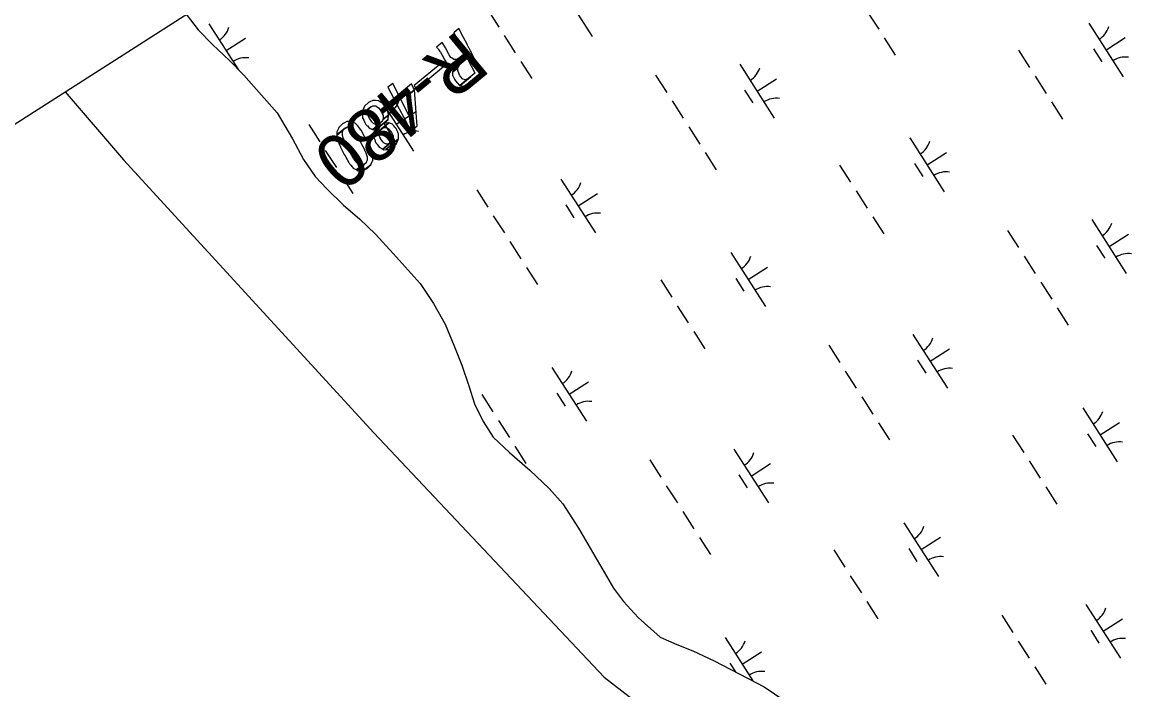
# Model space of a CAD drawing. Extents: x 3962991 to 3983549, y 181631 to 204078.
# Drawn here: x 3969173 to 3970044, y 198215 to 198737 of the extents above; entities that cross this region are included whole.
import ezdxf

# ---------------------------------------------------------------- set-up
doc = ezdxf.new("R2010")
doc.units = 0
for name, color, linetype in [('V-ANNO-MASK', 7, 'Continuous'), ('V-ANNO-MASK2', 7, 'Continuous'), ('V-GRID-FRAM', 7, 'Continuous'), ('V-RIVR-EDGE', 7, 'Continuous'), ('V-RIVR-RANG-IDEN', 7, 'Continuous'), ('V-WETL-SWMP', 7, 'Continuous')]:
    doc.layers.add(name, color=color, linetype=linetype)

msp = doc.modelspace()

# ---------------------------------------------------------------- linework, layer by layer
at = {"layer": 'V-ANNO-MASK2'}
for points in [[(3969516.05, 198730.03), (3969515.13, 198731.81), (3969511.16, 198728.53), (3969512.09, 198726.76), (3969512.29, 198726.38), (3969513.23, 198724.57), (3969513.52, 198724.02), (3969516.02, 198719.23), (3969516.33, 198718.63), (3969517.5, 198716.4), (3969517.98, 198715.47), (3969518.75, 198714), (3969519.3, 198712.94), (3969519.47, 198712.61), (3969519.62, 198712.33), (3969508.77, 198703.36), (3969510.4, 198703.21), (3969513.2, 198704.25), (3969511.77, 198702.61), (3969510.22, 198699.72), (3969510.22, 198699.34), (3969521.52, 198708.68), (3969521.61, 198708.51), (3969522.11, 198707.56), (3969522.93, 198706), (3969523.19, 198705.5), (3969524.82, 198702.38), (3969525.24, 198701.56), (3969526.46, 198699.23), (3969527.35, 198697.54), (3969527.53, 198697.18), (3969527.53, 198697.19), (3969527.61, 198697.04), (3969527.64, 198696.96), (3969515.98, 198687.33), (3969519.53, 198686.56), (3969523.1, 198687.89), (3969526.63, 198690.58), (3969533.62, 198696.36), (3969533.54, 198696.52), (3969532.96, 198697.65), (3969531.6, 198700.24), (3969531.57, 198700.31), (3969531.49, 198700.45), (3969531.3, 198700.81), (3969530.42, 198702.51), (3969529.2, 198704.83), (3969528.78, 198705.65), (3969527.15, 198708.77), (3969526.89, 198709.27), (3969526.07, 198710.84), (3969525.58, 198711.78), (3969525.49, 198711.95), (3969525.35, 198712.22), (3969524.76, 198713.34), (3969524.6, 198713.66), (3969524.13, 198714.55), (3969523.59, 198715.6), (3969523.44, 198715.89), (3969523.26, 198716.22), (3969522.71, 198717.28), (3969521.94, 198718.75), (3969521.46, 198719.67), (3969520.3, 198721.9), (3969519.98, 198722.51), (3969517.48, 198727.3), (3969517.2, 198727.84), (3969516.25, 198729.65)], [(3969503.1, 198719.33), (3969501.97, 198720.94), (3969497.64, 198717.37), (3969498.93, 198715.89), (3969499.17, 198715.55), (3969500.3, 198713.89), (3969500.6, 198713.35), (3969503.18, 198708.63), (3969503.5, 198708.03), (3969504.91, 198706), (3969505.49, 198705.16), (3969506.84, 198704.17), (3969507.8, 198703.45), (3969508.32, 198703.4), (3969508.77, 198703.36), (3969515.88, 198709.23), (3969513.61, 198707.77), (3969513.02, 198707.75), (3969511.09, 198707.68), (3969509.73, 198708.66), (3969508.87, 198709.27), (3969507.52, 198711.35), (3969507.16, 198711.92), (3969504.65, 198716.7), (3969504.35, 198717.23), (3969503.34, 198718.99)], [(3969503.14, 198702.19), (3969501.65, 198705.03), (3969480.2, 198687.32), (3969481.69, 198684.47)], [(3969515.76, 198703.67), (3969518.28, 198706), (3969510.22, 198699.34), (3969510.22, 198699.1), (3969510.21, 198697.74), (3969514.31, 198701.13)], [(3969514.39, 198698.95), (3969514.31, 198701.12), (3969510.21, 198697.74), (3969510.2, 198695.49), (3969510.44, 198694.98), (3969511.98, 198691.77), (3969512.37, 198690.93), (3969514.13, 198689.05), (3969515.42, 198687.68), (3969515.68, 198687.39), (3969515.89, 198687.35), (3969522.42, 198692.75), (3969521.82, 198692.46), (3969520.39, 198691.79), (3969518.13, 198692.35), (3969516.47, 198694.31), (3969515.89, 198695), (3969514.41, 198698.25)], [(3969524.44, 198694.32), (3969522.42, 198692.75), (3969515.89, 198687.35), (3969515.98, 198687.33)], [(3969467.85, 198680.2), (3969463.27, 198688.98), (3969459.6, 198685.94), (3969464.17, 198677.16)], [(3969479.66, 198685.15), (3969477.9, 198688.5), (3969460.48, 198674.11), (3969462.24, 198670.76), (3969476.75, 198682.74), (3969476.92, 198680.97), (3969480.36, 198683.82)], [(3969470.26, 198675.47), (3969469.59, 198676.83), (3969465.93, 198673.81), (3969466.63, 198672.48), (3969473.46, 198659.41), (3969473.63, 198659.06), (3969474.79, 198656.84), (3969474.85, 198656.73), (3969476.27, 198654), (3969479.34, 198656.53), (3969478.1, 198659.41), (3969478.05, 198659.53), (3969476.98, 198661.83), (3969476.81, 198662.18)], [(3969481.61, 198666.14), (3969480.36, 198683.81), (3969476.92, 198680.97), (3969478.46, 198663.54), (3969478.5, 198663.08), (3969478.83, 198660.17), (3969478.85, 198660.03), (3969479.34, 198656.53), (3969476.27, 198654), (3969477.51, 198651.64), (3969482.34, 198655.64), (3969482.12, 198658.83), (3969481.86, 198662.51), (3969481.85, 198662.67), (3969481.64, 198665.67)], [(3969445.31, 198674.55), (3969444.28, 198674.08), (3969441.21, 198671.16), (3969440.56, 198669.72), (3969439.26, 198666.8), (3969439.44, 198665.06), (3969446.09, 198670.55), (3969446.63, 198670.8), (3969446.68, 198670.82), (3969447.84, 198671.36), (3969448.72, 198671.33), (3969450.07, 198671.29), (3969450.68, 198670.88), (3969451.11, 198670.6), (3969452.22, 198669.85), (3969452.28, 198669.8), (3969453.42, 198668.2), (3969454.35, 198666.89), (3969454.38, 198666.84), (3969454.96, 198665.51), (3969455.08, 198665.23), (3969455.71, 198663.8), (3969455.76, 198662.43), (3969455.76, 198662.28), (3969455.8, 198661.13), (3969455.62, 198660.74), (3969460.15, 198664.48), (3969460.09, 198664.67), (3969459.78, 198665.6), (3969459.74, 198665.72), (3969459.38, 198666.83), (3969458.87, 198668.37), (3969458.77, 198668.66), (3969457.98, 198669.81), (3969457.95, 198669.85), (3969457.03, 198671.18), (3969455.91, 198672.8), (3969455.87, 198672.86), (3969454.78, 198673.63), (3969454.36, 198673.92), (3969453.76, 198674.34), (3969453, 198674.87), (3969452.51, 198675.21), (3969452.23, 198675.4), (3969452.21, 198675.41), (3969452, 198675.43), (3969449.88, 198675.57), (3969447.8, 198675.7)], [(3969444.79, 198669.28), (3969446.09, 198670.55), (3969439.45, 198665.06), (3969439.46, 198664.88), (3969439.46, 198664.88), (3969439.46, 198664.86), (3969444.68, 198669.17)], [(3969444.36, 198668.48), (3969444.68, 198669.17), (3969439.46, 198664.86), (3969439.5, 198664.47), (3969439.51, 198664.47), (3969439.57, 198663.78), (3969439.68, 198662.71), (3969439.77, 198661.87), (3969440, 198661.42), (3969440.59, 198660.25), (3969440.63, 198660.18), (3969441.54, 198658.39), (3969441.54, 198658.39), (3969442.29, 198656.92), (3969442.32, 198656.88), (3969443.29, 198655.88), (3969443.49, 198655.66), (3969443.5, 198655.67), (3969444.55, 198654.58), (3969445.3, 198653.8), (3969445.38, 198653.7), (3969446.4, 198653.36), (3969446.6, 198653.29), (3969447.01, 198653.15), (3969447.52, 198652.99), (3969447.67, 198652.93), (3969453.2, 198657.5), (3969452.78, 198657.33), (3969451.39, 198656.77), (3969450.89, 198656.83), (3969450.63, 198656.86), (3969449.38, 198657), (3969449.2, 198657.02), (3969448.32, 198657.7), (3969447.1, 198658.64), (3969446.94, 198658.88), (3969446.16, 198660.06), (3969446.14, 198660.1), (3969445.24, 198661.44), (3969444.45, 198663.34), (3969444.42, 198663.41), (3969443.9, 198664.64), (3969443.87, 198665.26), (3969443.84, 198666.14), (3969443.78, 198667.25)], [(3969425.57, 198658.16), (3969423.99, 198657.31), (3969421.21, 198654.57), (3969420.82, 198653.72), (3969419.52, 198650.95), (3969419.55, 198649.52), (3969419.56, 198648.67), (3969426.27, 198654.21), (3969426.55, 198654.32), (3969428.03, 198654.93), (3969428.63, 198654.85), (3969429.13, 198654.79), (3969430.08, 198654.67), (3969430.96, 198653.97), (3969430.97, 198653.96), (3969432.37, 198652.84), (3969433.11, 198651.74), (3969433.89, 198650.6), (3969434.71, 198649.4), (3969434.79, 198649.27), (3969437.51, 198644.28), (3969437.84, 198643.69), (3969438.45, 198642.55), (3969438.72, 198641.99), (3969438.73, 198641.99), (3969441.08, 198637.19), (3969441.08, 198637.2), (3969441.27, 198636.81), (3969441.82, 198635.69), (3969442.21, 198634.59), (3969442.76, 198633.01), (3969443.25, 198631.62), (3969443.26, 198631.49), (3969443.3, 198630.09), (3969443.31, 198629.48), (3969443.33, 198628.86), (3969442.88, 198627.9), (3969442.88, 198627.91), (3969442.43, 198626.94), (3969440.94, 198625.59), (3969435.35, 198620.97), (3969436.07, 198620.57), (3969437.53, 198620.6), (3969439.77, 198620.65), (3969441.42, 198621.53), (3969446.06, 198625.36), (3969446.4, 198626.13), (3969447.64, 198628.95), (3969447.62, 198630.11), (3969447.61, 198631.09), (3969447.6, 198631.22), (3969447.6, 198631.8), (3969447.58, 198632.38), (3969447.57, 198633), (3969447.42, 198633.49), (3969447.05, 198634.62), (3969447.02, 198634.73), (3969446.56, 198636.15), (3969446.03, 198637.75), (3969445.55, 198638.77), (3969445, 198639.9), (3969444.81, 198640.28), (3969442.49, 198645.1), (3969442.19, 198645.64), (3969441.57, 198646.77), (3969441.24, 198647.36), (3969438.48, 198652.32), (3969438.4, 198652.46), (3969437.53, 198653.61), (3969436.69, 198654.7), (3969435.89, 198655.74), (3969434.81, 198657.14), (3969434.81, 198657.15), (3969433.78, 198657.73), (3969433.12, 198658.09), (3969432.78, 198658.28), (3969432.37, 198658.52), (3969431.93, 198658.77), (3969431.84, 198658.81), (3969431.22, 198659.16), (3969429.44, 198659.15), (3969427.37, 198659.13)], [(3969460.08, 198663.95), (3969460.15, 198664.48), (3969455.62, 198660.74), (3969455.27, 198659.97), (3969454.82, 198659.02), (3969453.2, 198657.5), (3969447.67, 198652.94), (3969448.37, 198652.69), (3969450.31, 198652.96), (3969459.64, 198660.66), (3969459.84, 198662.17), (3969459.96, 198663.09), (3969459.99, 198663.29)], [(3969459.06, 198659.8), (3969459.63, 198660.66), (3969450.31, 198652.96), (3969450.88, 198653.04), (3969449.36, 198650.87), (3969448.95, 198650.29), (3969448.78, 198648.71), (3969460.18, 198658.13), (3969458.09, 198657.84), (3969457.73, 198657.79)], [(3969424.78, 198652.87), (3969426.27, 198654.21), (3969419.56, 198648.67), (3969419.56, 198648.56)], [(3969424.31, 198651.86), (3969424.78, 198652.86), (3969419.56, 198648.56), (3969419.57, 198647.95), (3969419.59, 198647.39), (3969419.59, 198646.92), (3969419.83, 198646.2), (3969420.2, 198645.09), (3969420.21, 198645.08), (3969420.8, 198643.28), (3969421.24, 198641.94), (3969421.85, 198640.66), (3969422.48, 198639.31), (3969422.49, 198639.31), (3969422.55, 198639.17), (3969425.01, 198633.96), (3969425.35, 198633.37), (3969425.98, 198632.25), (3969426.28, 198631.71), (3969428.88, 198627.12), (3969429.08, 198626.75), (3969429.85, 198625.8), (3969430.54, 198624.95), (3969431.53, 198623.73), (3969432.4, 198622.65), (3969432.46, 198622.57), (3969433.49, 198621.99), (3969433.5, 198622), (3969433.94, 198621.75), (3969434.41, 198621.49), (3969434.83, 198621.26), (3969439.21, 198624.87), (3969438.59, 198624.94), (3969437.92, 198625.03), (3969437.26, 198625.11), (3969436.36, 198625.8), (3969436.27, 198625.86), (3969435.14, 198626.71), (3969434.21, 198627.98), (3969433.56, 198628.87), (3969432.84, 198629.86), (3969432.59, 198630.19), (3969430.03, 198634.8), (3969429.73, 198635.34), (3969429.1, 198636.47), (3969428.8, 198637.09), (3969426.3, 198642.26), (3969426.23, 198642.4), (3969425.58, 198643.74), (3969425.08, 198645.11), (3969424.6, 198646.42), (3969423.96, 198648.18), (3969423.96, 198648.19), (3969423.92, 198649.58), (3969423.9, 198650.48), (3969423.89, 198650.94)], [(3969453.54, 198652.25), (3969454.98, 198653.6), (3969448.75, 198648.46), (3969448.72, 198648.27), (3969448.67, 198647.79), (3969448.57, 198646.98), (3969452.61, 198650.31), (3969453.2, 198651.53)], [(3969460.37, 198658.05), (3969460.18, 198658.13), (3969448.78, 198648.71), (3969448.75, 198648.46), (3969454.98, 198653.6), (3969455.44, 198653.82), (3969456.69, 198654.41), (3969457.52, 198654.37), (3969457.98, 198654.34), (3969457.99, 198654.34), (3969458.79, 198654.29), (3969459.32, 198653.89), (3969459.67, 198653.61), (3969459.68, 198653.62), (3969460.68, 198652.83), (3969461.42, 198651.83), (3969461.66, 198651.5), (3969462.3, 198650.63), (3969462.35, 198650.56), (3969463.08, 198648.96), (3969463.54, 198647.93), (3969463.54, 198647.89), (3969463.64, 198646.57), (3969463.65, 198646.57), (3969463.68, 198646.03), (3969463.71, 198645.68), (3969463.17, 198644.42), (3969463.18, 198644.42), (3969462.95, 198643.89), (3969461.47, 198642.44), (3969455.45, 198637.47), (3969456.16, 198637.06), (3969457.8, 198637.15), (3969467.91, 198645.49), (3969467.89, 198646.75), (3969467.87, 198647.73), (3969467.87, 198647.96), (3969467.87, 198648.29), (3969467.86, 198649.1), (3969467.85, 198649.47), (3969467.66, 198649.89), (3969467.19, 198650.9), (3969467.17, 198650.93), (3969466.7, 198651.95), (3969465.96, 198653.54), (3969465.92, 198653.62), (3969465.23, 198654.45), (3969464.97, 198654.76), (3969464.17, 198655.71), (3969463.37, 198656.66), (3969463.08, 198657), (3969462.4, 198657.27), (3969461.81, 198657.5), (3969461.47, 198657.63), (3969460.87, 198657.86), (3969460.5, 198658)], [(3969452.64, 198649.92), (3969452.61, 198650.31), (3969448.57, 198646.98), (3969448.52, 198646.53), (3969448.74, 198645.99), (3969449, 198645.37), (3969449.17, 198644.94), (3969449.66, 198643.73), (3969450.15, 198642.52), (3969450.4, 198642.2), (3969451.05, 198641.34), (3969451.1, 198641.27), (3969452.13, 198639.91), (3969452.78, 198639.05), (3969452.8, 198639.02), (3969453.8, 198638.44), (3969454.21, 198638.2), (3969454.47, 198638.05), (3969455.05, 198637.71), (3969455.29, 198637.57), (3969455.45, 198637.47), (3969461.47, 198642.45), (3969460.75, 198642.07), (3969459.66, 198641.52), (3969458.7, 198641.54), (3969458.26, 198641.55), (3969457.58, 198641.56), (3969456.65, 198642.2), (3969456.63, 198642.22), (3969455.69, 198642.86), (3969454.72, 198644.26), (3969454.67, 198644.33), (3969454.05, 198645.22), (3969453.88, 198645.6), (3969453.33, 198646.76), (3969452.78, 198647.92), (3969452.74, 198648.46), (3969452.69, 198649.25)], [(3969466.57, 198642.54), (3969467.91, 198645.49), (3969457.8, 198637.15), (3969460.18, 198637.27), (3969461.63, 198638.12), (3969466.32, 198641.99)], [(3969463.55, 198639.25), (3969466.31, 198641.99), (3969461.63, 198638.12)], [(3969440.63, 198625.46), (3969439.2, 198624.87), (3969434.83, 198621.26), (3969435.26, 198621.02), (3969435.35, 198620.97), (3969440.94, 198625.59)], [(3969443.18, 198622.46), (3969446.06, 198625.36), (3969441.42, 198621.53), (3969443.17, 198622.45)]]:
    msp.add_lwpolyline(points, close=True, dxfattribs=at)
at = {"layer": 'V-GRID-FRAM'}
msp.add_lwpolyline([(3973881.07, 201670.74), (3982001.83, 189003.7), (3974929.17, 184418.27), (3966825.38, 197159.8), (3973881.07, 201670.74)], dxfattribs=at)
at = {"layer": 'V-RIVR-EDGE'}
msp.add_lwpolyline([(3969206.8, 198682.32), (3969252.51, 198629.16), (3969448.4, 198415.46), (3969628.85, 198224.32), (3969670.41, 198192.26), (3969837.8, 198074.73), (3969909.03, 198027.24), (3970014.7, 197972.63), (3970121.55, 197919.21), (3970196.34, 197891.9), (3970259.26, 197890.71), (3970295.75, 197917.75), (3970339.58, 197927.32)], dxfattribs=at)
at = {"layer": 'V-WETL-SWMP'}
for p, q in [((3969592.53, 198767.84), (3969619.52, 198725.75)), ((3969537.63, 198746.54), (3969546.26, 198733.07)), ((3969301.72, 198743.01), (3969310.89, 198730.84)), ((3969835.04, 198744.78), (3969843.67, 198731.31)), ((3969310.89, 198730.84), (3969322.29, 198719.36)), ((3969319.47, 198735.61), (3969342.53, 198699.65)), ((3970008.04, 198736.12), (3970035.02, 198694.03)), ((3969332.97, 198714.56), (3969348.12, 198724.28)), ((3969550.58, 198726.34), (3969559.21, 198712.87)), ((3969847.99, 198724.57), (3969856.62, 198711.1)), ((3970021.53, 198715.07), (3970036.68, 198724.79)), ((3969322.29, 198719.36), (3969335.47, 198706.75)), ((3969953.13, 198714.82), (3969961.77, 198701.35)), ((3970011.79, 198715.96), (3970018.27, 198705.86)), ((3969335.47, 198706.75), (3969346.87, 198695.27)), ((3969563.53, 198706.13), (3969572.17, 198692.66)), ((3969734.98, 198703.89), (3969761.96, 198661.8)), ((3969346.87, 198695.27), (3969360.71, 198679.75)), ((3969669.1, 198695.41), (3969677.73, 198681.94)), ((3969966.08, 198694.62), (3969974.72, 198681.15)), ((3969748.47, 198682.84), (3969763.63, 198692.56)), ((3969360.71, 198679.75), (3969372.74, 198665.94)), ((3969452.5, 198678.07), (3969479.48, 198635.97)), ((3969738.74, 198683.73), (3969745.22, 198673.63)), ((3969682.05, 198675.21), (3969690.69, 198661.74)), ((3969979.04, 198674.41), (3969987.67, 198660.94)), ((3969372.74, 198665.94), (3969384.92, 198645.68)), ((3969465.99, 198657.02), (3969481.14, 198666.73)), ((3969397.59, 198656.77), (3969406.23, 198643.3)), ((3969456.26, 198657.91), (3969462.73, 198647.8)), ((3969695, 198655), (3969703.64, 198641.54)), ((3969384.92, 198645.68), (3969393.49, 198629.45)), ((3969868, 198646.35), (3969894.99, 198604.25)), ((3969410.55, 198636.56), (3969419.18, 198623.09)), ((3969707.96, 198634.8), (3969716.59, 198621.33)), ((3969881.5, 198625.3), (3969896.65, 198635.01)), ((3969393.49, 198629.45), (3969402.59, 198616.17)), ((3969813.1, 198625.05), (3969821.73, 198611.58)), ((3969871.76, 198626.19), (3969878.24, 198616.08)), ((3969402.59, 198616.17), (3969411.6, 198606.4)), ((3969423.5, 198616.36), (3969432.13, 198602.89)), ((3969594.95, 198614.11), (3969621.93, 198572.02)), ((3969411.6, 198606.4), (3969424.78, 198593.79)), ((3969529.07, 198605.64), (3969537.7, 198592.17)), ((3969608.44, 198593.07), (3969623.59, 198602.78)), ((3969826.05, 198604.85), (3969834.69, 198591.38)), ((3969424.78, 198593.79), (3969437.34, 198582.92)), ((3969598.71, 198593.96), (3969605.18, 198583.85)), ((3969437.34, 198582.92), (3969449.93, 198570.89)), ((3969542.02, 198585.44), (3969550.66, 198571.97)), ((3969839, 198584.64), (3969847.64, 198571.17)), ((3970010.45, 198582.4), (3970037.44, 198540.3)), ((3969944.57, 198573.92), (3969953.21, 198560.45)), ((3969449.93, 198570.89), (3969463.75, 198555.94)), ((3969554.97, 198565.23), (3969563.61, 198551.76)), ((3970023.95, 198561.35), (3970039.1, 198571.06)), ((3969463.75, 198555.94), (3969484.8, 198532.37)), ((3969727.97, 198556.57), (3969754.96, 198514.48)), ((3970014.21, 198562.24), (3970020.69, 198552.13)), ((3969957.53, 198553.72), (3969966.16, 198540.25)), ((3969567.93, 198545.03), (3969576.56, 198531.56)), ((3969741.46, 198535.53), (3969756.62, 198545.24)), ((3969484.8, 198532.37), (3969495.12, 198516.76)), ((3969673.07, 198535.28), (3969681.7, 198521.81)), ((3969731.73, 198536.41), (3969738.21, 198526.31)), ((3969970.48, 198533.51), (3969979.11, 198520.04)), ((3969495.12, 198516.76), (3969504.27, 198500.54)), ((3969686.02, 198515.07), (3969694.66, 198501.6)), ((3969983.43, 198513.31), (3969992.07, 198499.84)), ((3969504.27, 198500.54), (3969511.08, 198484.27)), ((3969698.97, 198494.87), (3969707.61, 198481.4)), ((3969870.42, 198492.62), (3969897.41, 198450.53)), ((3969511.08, 198484.27), (3969517.3, 198468.58)), ((3969804.54, 198484.15), (3969813.18, 198470.68)), ((3969883.91, 198471.58), (3969899.07, 198481.29)), ((3969517.3, 198468.58), (3969522.94, 198452.28)), ((3969874.18, 198472.46), (3969880.66, 198462.36)), ((3969587.94, 198466.8), (3969614.93, 198424.71)), ((3969817.49, 198463.94), (3969826.13, 198450.47)), ((3969522.94, 198452.28), (3969527.36, 198438.3)), ((3969601.43, 198445.75), (3969616.59, 198455.47)), ((3969533.04, 198445.5), (3969541.67, 198432.03)), ((3969591.7, 198446.64), (3969598.18, 198436.54)), ((3969830.45, 198443.74), (3969839.08, 198430.27)), ((3969527.36, 198438.3), (3969534.12, 198424.38)), ((3970003.45, 198435.08), (3970030.43, 198392.99)), ((3969534.12, 198424.38), (3969542.01, 198412.24)), ((3969545.99, 198425.3), (3969554.62, 198411.83)), ((3969843.4, 198423.53), (3969852.03, 198410.06)), ((3970016.94, 198414.03), (3970032.09, 198423.75)), ((3969542.01, 198412.24), (3969554.6, 198400.2)), ((3969948.54, 198413.78), (3969957.18, 198400.31)), ((3970007.2, 198414.92), (3970013.68, 198404.82)), ((3969554.6, 198400.2), (3969570.73, 198386.48)), ((3969558.94, 198405.09), (3969567.58, 198391.62)), ((3969730.39, 198402.85), (3969757.37, 198360.76)), ((3969664.51, 198394.37), (3969673.14, 198380.9)), ((3969743.88, 198381.8), (3969759.04, 198391.52)), ((3969961.49, 198393.58), (3969970.13, 198380.11)), ((3969570.73, 198386.48), (3969585.71, 198372.15)), ((3969734.15, 198382.69), (3969740.63, 198372.59)), ((3969585.71, 198372.15), (3969596.54, 198360.08)), ((3969677.46, 198374.17), (3969686.1, 198360.7)), ((3969974.45, 198373.37), (3969983.08, 198359.9)), ((3969596.54, 198360.08), (3969608.69, 198340.99)), ((3969690.41, 198353.96), (3969699.05, 198340.5)), ((3969608.69, 198340.99), (3969636.13, 198294.1)), ((3969863.41, 198345.31), (3969890.4, 198303.21)), ((3969703.37, 198333.76), (3969712, 198320.29)), ((3969876.91, 198324.26), (3969892.06, 198333.97)), ((3969808.51, 198324.01), (3969817.14, 198310.54)), ((3969867.17, 198325.15), (3969873.65, 198315.04)), ((3969821.46, 198303.81), (3969830.1, 198290.34)), ((3969636.13, 198294.1), (3969643.98, 198283.72)), ((3969643.98, 198283.72), (3969655.41, 198271.07)), ((3969834.41, 198283.6), (3969843.05, 198270.13)), ((3970005.86, 198281.36), (3970032.85, 198239.26)), ((3969655.41, 198271.07), (3969672.76, 198255.62)), ((3969939.98, 198272.88), (3969948.62, 198259.41)), ((3970019.36, 198260.31), (3970034.51, 198270.02)), ((3970009.62, 198261.2), (3970016.1, 198251.09)), ((3969672.76, 198255.62), (3969685.79, 198250.04)), ((3969685.79, 198250.04), (3969698.21, 198245.04)), ((3969723.38, 198255.53), (3969745.21, 198221.48)), ((3969952.94, 198252.68), (3969961.57, 198239.21)), ((3969698.21, 198245.04), (3969714.81, 198237.2)), ((3969736.87, 198234.49), (3969752.03, 198244.2)), ((3969714.81, 198237.2), (3969753.97, 198216.96)), ((3969727.14, 198235.37), (3969731.5, 198228.57)), ((3969965.89, 198232.47), (3969974.52, 198219)), ((3969753.97, 198216.96), (3969778.98, 198199.92))]:
    msp.add_line(p, q, dxfattribs=at)
for centre, start, end in [((3969318.26, 198737.94), 301.89187, 343.43553), ((3970006.82, 198738.45), 301.89187, 343.43553), ((3969348.07, 198691.44), 81.89186, 123.43552), ((3970036.64, 198691.95), 81.89186, 123.43552), ((3969733.76, 198706.22), 301.89187, 343.43553), ((3969763.58, 198659.72), 81.89186, 123.43552), ((3969451.28, 198680.4), 301.89187, 343.43553), ((3969481.1, 198633.89), 81.89186, 123.43552), ((3969866.79, 198648.68), 301.89187, 343.43553), ((3969896.6, 198602.17), 81.89186, 123.43552), ((3969593.73, 198616.45), 301.89187, 343.43553), ((3969623.55, 198569.94), 81.89186, 123.43552), ((3970009.24, 198584.73), 301.89187, 343.43553), ((3970039.05, 198538.22), 81.89186, 123.43552), ((3969726.76, 198558.91), 301.89187, 343.43553), ((3969756.57, 198512.4), 81.89186, 123.43552), ((3969869.21, 198494.96), 301.89187, 343.43553), ((3969586.73, 198469.13), 301.89187, 343.43553), ((3969899.02, 198448.45), 81.89186, 123.43552), ((3969616.54, 198422.63), 81.89186, 123.43552), ((3970002.23, 198437.41), 301.89187, 343.43553), ((3970032.05, 198390.91), 81.89186, 123.43552), ((3969729.17, 198405.18), 301.89187, 343.43553), ((3969758.99, 198358.68), 81.89186, 123.43552), ((3969862.2, 198347.64), 301.89187, 343.43553), ((3969892.01, 198301.13), 81.89186, 123.43552), ((3970004.65, 198283.69), 301.89187, 343.43553), ((3969722.17, 198257.87), 301.89187, 343.43553), ((3970034.46, 198237.18), 81.89186, 123.43552), ((3969751.98, 198211.36), 81.89186, 123.43552)]:
    msp.add_arc(centre, 17.62, start, end, dxfattribs=at)

# ---------------------------------------------------------------- texts
at = {"layer": 'V-ANNO-MASK'}
msp.add_text('R-480  ', height=41.5, rotation=219.55434, dxfattribs=at).set_placement((3969514.64, 198731.41))
at = {"layer": 'V-RIVR-RANG-IDEN'}
msp.add_text('R-480  ', height=41.5, rotation=219.55434, dxfattribs=at).set_placement((3969514.64, 198731.41))

doc.saveas('drawing.dxf')
